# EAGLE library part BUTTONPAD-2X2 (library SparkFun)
5mm Button Pad Proven layout and schematic for 2x2 button pad. Panelize this device/fp to a 4x4 pad if needed. Spark Fun Electronics SKU : ButtonPad-4x4. Compatible common cathode tri-color LED SKU : Comp-TPL
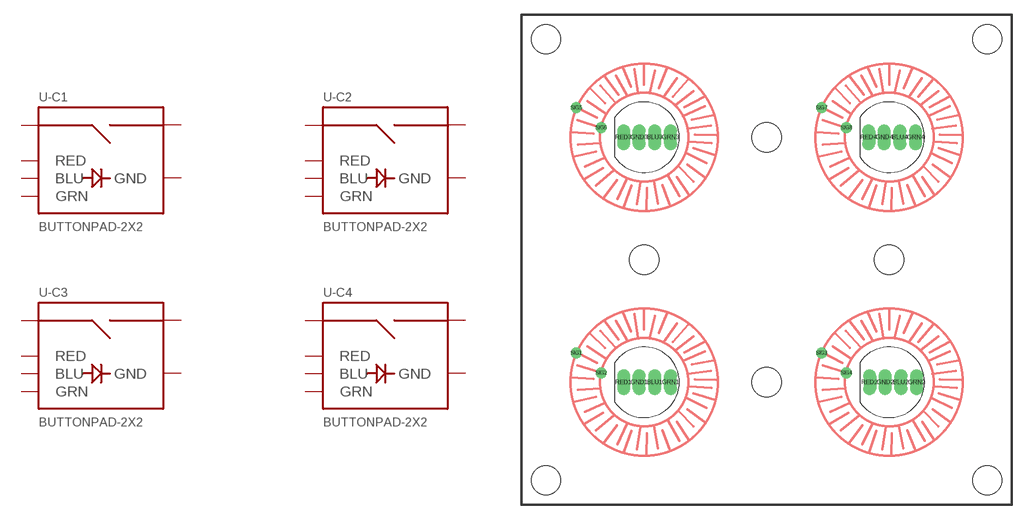
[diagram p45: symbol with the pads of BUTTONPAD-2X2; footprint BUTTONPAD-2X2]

Designator prefix -; gates -C1=BUTTONPAD_SINGLE -C2=BUTTONPAD_SINGLE -C3=BUTTONPAD_SINGLE -C4=BUTTONPAD_SINGLE

## BUTTONPAD-2X22X2  [BUTTONPAD-2X2]
BLU1  -C1:BLU
BLU2  -C2:BLU
BLU3  -C3:BLU
BLU4  -C4:BLU
GND1  -C1:GND
GND2  -C2:GND
GND3  -C3:GND
GND4  -C4:GND
GRN1  -C1:GRN
GRN2  -C2:GRN
GRN3  -C3:GRN
GRN4  -C4:GRN
RED1  -C1:RED
RED2  -C2:RED
RED3  -C3:RED
RED4  -C4:RED
SIG1  -C1:SIG1
SIG2  -C1:SIG2
SIG3  -C2:SIG1
SIG4  -C2:SIG2
SIG5  -C3:SIG1
SIG6  -C3:SIG2
SIG7  -C4:SIG1
SIG8  -C4:SIG2

## Footprint BUTTONPAD-2X2 (pad centres in mm)
drill 0.8 pad 1.016 long: BLU1 13.6,12.5; BLU2 38.7,12.5; BLU3 13.6,37.5; BLU4 38.6,37.5; GND1 12,12.5; GND2 37.1,12.5; GND3 12,37.5; GND4 37,37.5; GRN1 15.2,12.5; GRN2 40.3,12.5; GRN3 15.2,37.5; GRN4 40.2,37.5; RED2 35.5,12.5; RED3 10.4,37.5; RED4 35.4,37.5
drill 0.8 long: RED1 10.4,12.5
drill 0.6 round: SIG1 5.588,15.494; SIG2 8.128,13.462; SIG3 30.607,15.494; SIG4 33.147,13.462; SIG5 5.588,40.513; SIG6 8.128,38.481; SIG7 30.607,40.513; SIG8 33.147,38.481
hole 3 at 12.5,25
hole 3 at 25,37.5
hole 3 at 37.5,25
hole 3 at 25,12.5
hole 3 at 2.5,2.5
hole 3 at 2.5,47.5
hole 3 at 47.5,47.5
hole 3 at 47.5,2.5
